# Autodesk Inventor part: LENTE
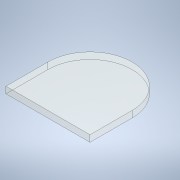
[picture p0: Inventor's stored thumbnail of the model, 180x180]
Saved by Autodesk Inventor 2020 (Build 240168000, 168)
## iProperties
Created: 2022-09
Part Number: LENTE
Material: Vidrio
Document SubType Name: Modeling
Designer: SEBAS
Density: 2.18 g/cm^3
Appearance: Claro
Author: SEBAS
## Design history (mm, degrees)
sketch "Boceto1"
  geometry: L1 (32, 0)-(-32, 0); L2 (32, 0)-(32, 32); L3 (-32, 32)-(-32, 0); L4 (32, 32)-(-32, 32); A1 r 32 centre (0, 0) between (-32, 0) and (32, 0); 1 further point
  constraints: 8 end point, 2 point on circle, 2 vertical alignment, 1 centre point, 1 coincident, 1 horizontal, 1 horizontal alignment
  dimensions: "d0" = 64 diameter of A1; "d1" = 32 distance of L1.start L2.end; "d2" = 64 distance between parallel lines of L3 L2
extrude "Extrusión1" new body sketch "Boceto1" distance "d3" = 5; taper "d4" = 0 deg
node "Sólido1"
